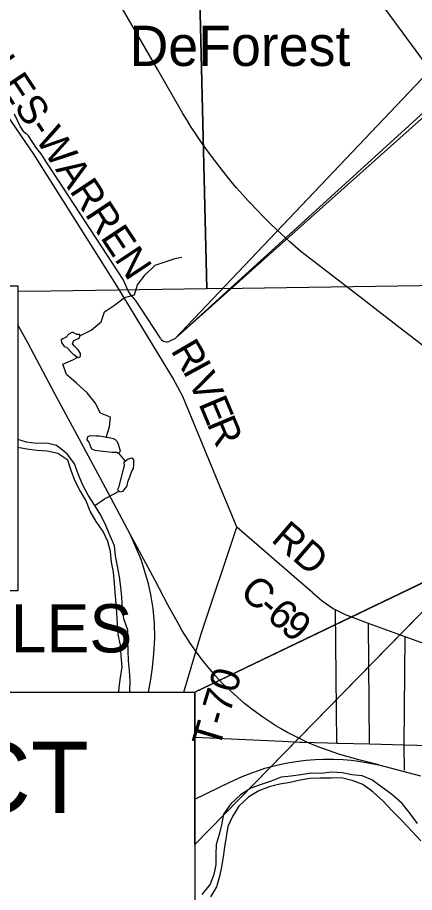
# Model space of a CAD drawing. Extents: x -37878.7 to -37844.7, y -19791.4 to -19769.4.
# Drawn here: x -37874.132 to -37873.351, y -19775.898 to -19774.18 of the extents above; entities that cross this region are included whole.
import ezdxf

# ---------------------------------------------------------------- set-up
doc = ezdxf.new("R2010")
doc.units = 0
for name, color, linetype in [('GM_X_City_Street', 7, 'Continuous'), ('GM_X_Corporation_Text', 7, 'Continuous'), ('GM_X_County_Road', 7, 'Continuous'), ('GM_X_County_Road_Text', 7, 'Continuous'), ('GM_X_Major_River', 7, 'Continuous'), ('GM_X_Minor_Lake', 7, 'Continuous'), ('GM_X_Minor_River', 7, 'Continuous'), ('GM_X_Rail_Line', 7, 'Continuous'), ('GM_X_Section', 7, 'Continuous'), ('GM_X_State_Route', 7, 'Continuous'), ('GM_X_Township_Road', 7, 'Continuous'), ('GM_X_Township_Road_Text', 7, 'Continuous'), ('GM_X_Unincorporated_Text', 7, 'Continuous'), ('SH_Data', 7, 'Continuous'), ('TX_P_1', 7, 'Continuous')]:
    doc.layers.add(name, color=color, linetype=linetype)

msp = doc.modelspace()

# ---------------------------------------------------------------- linework, layer by layer
at = {"layer": 'GM_X_City_Street'}
for points in [[(-37873.7707, -19775.3902), (-37873.7007, -19775.1805)], [(-37873.5041, -19775.6045), (-37873.5066, -19775.3431)], [(-37872.8734, -19775.5892), (-37872.8726, -19775.5759), (-37872.9176, -19775.5597), (-37872.9445, -19775.5501), (-37872.9852, -19775.5354), (-37873.0665, -19775.5062), (-37873.0787, -19775.5018), (-37873.1187, -19775.4876), (-37873.1691, -19775.4696), (-37873.1714, -19775.4688), (-37873.1939, -19775.4605), (-37873.2323, -19775.4464), (-37873.2421, -19775.4428), (-37873.301, -19775.4211), (-37873.3699, -19775.3957), (-37873.4414, -19775.3694), (-37873.4869, -19775.3527)], [(-37873.44, -19775.6062), (-37873.4414, -19775.3694)], [(-37873.3713, -19775.608), (-37873.3699, -19775.3957)], [(-37873.5222, -19775.6041), (-37873.5221, -19775.6041), (-37873.5041, -19775.6045), (-37873.5023, -19775.6046)], [(-37873.5023, -19775.6046), (-37873.44, -19775.6062), (-37873.3713, -19775.608), (-37873.2964, -19775.6099), (-37873.2652, -19775.6107), (-37873.2215, -19775.6119), (-37873.1559, -19775.6136), (-37873.1168, -19775.6146), (-37873.0689, -19775.6158), (-37872.9847, -19775.618), (-37872.9476, -19775.6187), (-37872.8753, -19775.6204)], [(-37873.3711, -19775.6581), (-37873.3713, -19775.608)]]:
    msp.add_lwpolyline(points, dxfattribs=at)
at = {"layer": 'GM_X_County_Road'}
for points in [[(-37873.7294, -19775.1112), (-37873.8071, -19774.9241), (-37873.8262, -19774.887), (-37873.9371, -19774.7051), (-37874.1, -19774.4477), (-37874.2922, -19774.1683), (-37874.3166, -19774.1461), (-37874.4179, -19774.0787)], [(-37873.5735, -19775.2907), (-37873.7007, -19775.1805), (-37873.7107, -19775.1562), (-37873.7294, -19775.1112)], [(-37873.5514, -19775.3098), (-37873.5733, -19775.2908), (-37873.5735, -19775.2907)], [(-37873.4869, -19775.3527), (-37873.5066, -19775.3431), (-37873.5113, -19775.3409), (-37873.5328, -19775.3259), (-37873.5512, -19775.31), (-37873.5514, -19775.3098)], [(-37873.7835, -19775.5929), (-37873.6118, -19775.601)], [(-37873.6118, -19775.601), (-37873.6117, -19775.601), (-37873.5769, -19775.6026), (-37873.572, -19775.6028)], [(-37873.572, -19775.6028), (-37873.5719, -19775.6028), (-37873.5222, -19775.6041)]]:
    msp.add_lwpolyline(points, dxfattribs=at)
at = {"layer": 'GM_X_Major_River'}
for points in [[(-37873.9135, -19775.4421), (-37873.9146, -19775.4228), (-37873.9147, -19775.4019), (-37873.9147, -19775.3826), (-37873.9228, -19775.3607), (-37873.9255, -19775.3395), (-37873.9267, -19775.3179), (-37873.929, -19775.2986), (-37873.9317, -19775.2778), (-37873.9355, -19775.257), (-37873.939, -19775.2366), (-37873.9413, -19775.2173), (-37873.9497, -19775.1978), (-37873.9581, -19775.1771), (-37873.9683, -19775.1572), (-37873.9797, -19775.1377), (-37873.9927, -19775.1175), (-37874.0033, -19775.098), (-37874.0117, -19775.0776), (-37874.0201, -19775.0562), (-37874.0341, -19775.0368), (-37874.0553, -19775.0201), (-37874.0744, -19775.0156), (-37874.0948, -19775.0164), (-37874.1146, -19775.0134), (-37874.131, -19775.0086)], [(-37873.949, -19775.2285), (-37873.9544, -19775.2089), (-37873.9635, -19775.1889), (-37873.9772, -19775.1691), (-37873.989, -19775.1493), (-37873.9974, -19775.1278), (-37874.0095, -19775.108), (-37874.019, -19775.0888), (-37874.0263, -19775.0692), (-37874.0331, -19775.0489), (-37874.0527, -19775.036), (-37874.0737, -19775.0312), (-37874.093, -19775.0297), (-37874.1139, -19775.0275), (-37874.131, -19775.0239)], [(-37873.9324, -19775.5045), (-37873.9321, -19775.4945), (-37873.9294, -19775.4755), (-37873.9261, -19775.4545), (-37873.9284, -19775.4333), (-37873.9296, -19775.4121), (-37873.9339, -19775.391), (-37873.9354, -19775.3697), (-37873.9363, -19775.3489), (-37873.9382, -19775.3296), (-37873.9397, -19775.3095), (-37873.9409, -19775.2902), (-37873.9429, -19775.269), (-37873.9471, -19775.2493), (-37873.949, -19775.2285)], [(-37873.9112, -19775.5045), (-37873.911, -19775.5032), (-37873.9103, -19775.483), (-37873.9119, -19775.4622), (-37873.9135, -19775.4421)], [(-37873.3456, -19775.7627), (-37873.3597, -19775.7429), (-37873.3753, -19775.7235), (-37873.3965, -19775.705), (-37873.4157, -19775.6914), (-37873.435, -19775.6766), (-37873.4541, -19775.6687), (-37873.4742, -19775.6668), (-37873.4936, -19775.6631), (-37873.5144, -19775.662), (-37873.5349, -19775.6643), (-37873.5542, -19775.6636), (-37873.5746, -19775.6671), (-37873.5938, -19775.6698), (-37873.6135, -19775.6717), (-37873.633, -19775.6794), (-37873.653, -19775.6862), (-37873.6733, -19775.6931), (-37873.6931, -19775.7065), (-37873.7124, -19775.7239), (-37873.7271, -19775.7444), (-37873.7309, -19775.7653), (-37873.7354, -19775.7844), (-37873.7414, -19775.8039), (-37873.7418, -19775.8236), (-37873.7417, -19775.843), (-37873.7459, -19775.8624), (-37873.753, -19775.8819), (-37873.7693, -19775.902)], [(-37873.3385, -19775.7964), (-37873.3567, -19775.7774), (-37873.3761, -19775.7569), (-37873.3954, -19775.7376), (-37873.4136, -19775.7179), (-37873.4333, -19775.7005), (-37873.453, -19775.6857), (-37873.472, -19775.6789), (-37873.4949, -19775.673), (-37873.515, -19775.6734), (-37873.5358, -19775.6735), (-37873.5562, -19775.6739), (-37873.5759, -19775.6777), (-37873.5955, -19775.682), (-37873.6163, -19775.6851), (-37873.637, -19775.6904), (-37873.6577, -19775.6981), (-37873.6771, -19775.7099), (-37873.6968, -19775.7282), (-37873.7092, -19775.7485), (-37873.7183, -19775.7685), (-37873.7217, -19775.7887), (-37873.7246, -19775.8092), (-37873.7273, -19775.8282), (-37873.731, -19775.8477), (-37873.7344, -19775.8667), (-37873.7408, -19775.887), (-37873.7525, -19775.9066)]]:
    msp.add_lwpolyline(points, dxfattribs=at)
at = {"layer": 'GM_X_Minor_Lake'}
for p, q in [((-37874.0359, -19774.8273), (-37874.0227, -19774.8407)), ((-37873.9756, -19775.0302), (-37873.946, -19775.033)), ((-37873.9219, -19775.0594), (-37873.9335, -19775.1025))]:
    msp.add_line(p, q, dxfattribs=at)
for points in [[(-37874.0227, -19774.8407), (-37874.0193, -19774.8429), (-37874.0151, -19774.8458), (-37874.012, -19774.8473), (-37874.0083, -19774.8453), (-37874.0084, -19774.8396), (-37874.0127, -19774.8321), (-37874.0158, -19774.8292), (-37874.0204, -19774.8243), (-37874.0235, -19774.8206), (-37874.0214, -19774.8141), (-37874.0109, -19774.8093), (-37874.0091, -19774.8062), (-37874.0092, -19774.8021), (-37874.0156, -19774.8018), (-37874.0225, -19774.7982), (-37874.0248, -19774.7982), (-37874.0308, -19774.8014), (-37874.036, -19774.8072), (-37874.0431, -19774.8108), (-37874.0461, -19774.8123), (-37874.0456, -19774.8188), (-37874.0421, -19774.8225), (-37874.0401, -19774.8255), (-37874.0359, -19774.8273)], [(-37873.946, -19775.033), (-37873.9369, -19775.0335), (-37873.9338, -19775.0361), (-37873.9293, -19775.0315), (-37873.9317, -19775.0247), (-37873.9326, -19775.0198), (-37873.9354, -19775.0126), (-37873.9393, -19775.0089), (-37873.9431, -19775.0067), (-37873.9488, -19775.0057), (-37873.9598, -19775.0037), (-37873.9709, -19775.002), (-37873.9777, -19775.0018), (-37873.9891, -19775.0013), (-37873.9943, -19775.0029), (-37873.9953, -19775.009), (-37873.9918, -19775.0138), (-37873.9886, -19775.0221), (-37873.9866, -19775.0266), (-37873.9801, -19775.0291), (-37873.9756, -19775.0302)], [(-37873.9335, -19775.1025), (-37873.9353, -19775.1067), (-37873.9307, -19775.1112), (-37873.9239, -19775.1095), (-37873.9165, -19775.0995), (-37873.9148, -19775.0915), (-37873.9112, -19775.0816), (-37873.9069, -19775.0705), (-37873.904, -19775.0651), (-37873.903, -19775.0575), (-37873.9032, -19775.0484), (-37873.9071, -19775.045), (-37873.9146, -19775.0471), (-37873.9194, -19775.0506), (-37873.9228, -19775.0537), (-37873.9219, -19775.0594)]]:
    msp.add_lwpolyline(points, dxfattribs=at)
at = {"layer": 'GM_X_Minor_River'}
for points in [[(-37874.0091, -19774.8049), (-37873.9874, -19774.7936), (-37873.9676, -19774.7773), (-37873.9612, -19774.7578), (-37873.9414, -19774.7444), (-37873.9213, -19774.7292), (-37873.9021, -19774.7239), (-37873.8957, -19774.7044), (-37873.8806, -19774.6851), (-37873.8613, -19774.6661), (-37873.8413, -19774.6592), (-37873.8217, -19774.6531), (-37873.8085, -19774.6505)], [(-37873.9575, -19775.0041), (-37873.9508, -19774.9837), (-37873.9493, -19774.9647), (-37873.9688, -19774.9564), (-37873.9791, -19774.9361), (-37873.995, -19774.9168), (-37874.0159, -19774.8978), (-37874.0355, -19774.8804), (-37874.0428, -19774.8605), (-37874.0233, -19774.8521), (-37874.0136, -19774.8465)], [(-37873.9194, -19775.0506), (-37873.9327, -19775.035)], [(-37873.9797, -19775.1377), (-37873.9607, -19775.1251), (-37873.9408, -19775.1145), (-37873.933, -19775.109)]]:
    msp.add_lwpolyline(points, dxfattribs=at)
at = {"layer": 'GM_X_Rail_Line'}
for points in [[(-37873.3122, -19774.8417), (-37873.3795, -19774.7897), (-37873.4588, -19774.7284), (-37873.5577, -19774.6519), (-37873.5746, -19774.6392), (-37873.5963, -19774.6202), (-37873.6133, -19774.6044), (-37873.6329, -19774.5861), (-37873.6457, -19774.5735), (-37873.6635, -19774.5552), (-37873.6712, -19774.5467), (-37873.6787, -19774.5388), (-37873.6898, -19774.527), (-37873.7014, -19774.5143), (-37873.7093, -19774.5048), (-37873.7193, -19774.4925), (-37873.7287, -19774.4801), (-37873.742, -19774.463), (-37873.7544, -19774.4468), (-37873.7685, -19774.4271), (-37873.7809, -19774.409), (-37873.7902, -19774.3946), (-37873.7977, -19774.3827), (-37873.807, -19774.3678), (-37873.8563, -19774.2826), (-37873.8975, -19774.2112), (-37873.9462, -19774.1259)], [(-37873.9096, -19775.1957), (-37873.9644, -19775.0935), (-37874.0155, -19774.9987), (-37874.0585, -19774.9186), (-37874.1117, -19774.8187), (-37874.131, -19774.7828)], [(-37873.4214, -19775.6474), (-37873.4607, -19775.6372), (-37873.4979, -19775.6271), (-37873.5225, -19775.6187), (-37873.5425, -19775.6113), (-37873.5614, -19775.6035), (-37873.6021, -19775.583), (-37873.6147, -19775.576), (-37873.6237, -19775.5707), (-37873.6497, -19775.5538), (-37873.6688, -19775.5399), (-37873.6847, -19775.5276), (-37873.6989, -19775.5153), (-37873.7139, -19775.5016), (-37873.7286, -19775.4873), (-37873.7423, -19775.4726), (-37873.7533, -19775.4603), (-37873.7638, -19775.4476), (-37873.773, -19775.4357), (-37873.7801, -19775.4261), (-37873.7925, -19775.4082), (-37873.8018, -19775.3939), (-37873.8088, -19775.3825), (-37873.8147, -19775.3714), (-37873.8354, -19775.3342), (-37873.8614, -19775.2855), (-37873.9014, -19775.211), (-37873.9096, -19775.1957)], [(-37873.8746, -19775.5045), (-37873.8698, -19775.4796), (-37873.8663, -19775.4561), (-37873.8636, -19775.4289), (-37873.8619, -19775.3988), (-37873.8626, -19775.3692), (-37873.865, -19775.3402), (-37873.87, -19775.313), (-37873.8746, -19775.2916), (-37873.8814, -19775.2675), (-37873.8889, -19775.2443), (-37873.9096, -19775.1957)], [(-37873.7835, -19775.7147), (-37873.7147, -19775.6816), (-37873.7003, -19775.6747), (-37873.6899, -19775.6703), (-37873.6795, -19775.666), (-37873.6694, -19775.6621), (-37873.6583, -19775.6583), (-37873.6454, -19775.6541), (-37873.6324, -19775.6506), (-37873.6195, -19775.6474), (-37873.6041, -19775.644), (-37873.5927, -19775.6421), (-37873.5794, -19775.64), (-37873.5642, -19775.6384), (-37873.5465, -19775.637), (-37873.5305, -19775.6362), (-37873.5103, -19775.6362), (-37873.4916, -19775.6369), (-37873.4759, -19775.638), (-37873.4614, -19775.6402), (-37873.446, -19775.6424), (-37873.4214, -19775.6474)], [(-37873.4214, -19775.6474), (-37873.3397, -19775.6689)]]:
    msp.add_lwpolyline(points, dxfattribs=at)
at = {"layer": 'GM_X_Section'}
for points in [[(-37872.1869, -19774.0898), (-37872.1703, -19774.6795), (-37872.5802, -19774.6904), (-37872.9663, -19774.7007), (-37873.2969, -19774.7059), (-37873.6902, -19774.7116), (-37873.7599, -19774.7127), (-37873.7756, -19774.0615), (-37873.0522, -19774.0492), (-37872.2676, -19774.0343)], [(-37875.1274, -19774.7063), (-37875.1291, -19774.6153), (-37875.1389, -19774.0828), (-37873.8639, -19774.0628), (-37873.7756, -19774.0615), (-37873.7599, -19774.7127), (-37874.0664, -19774.7168), (-37874.131, -19774.7175)]]:
    msp.add_lwpolyline(points, dxfattribs=at)
at = {"layer": 'GM_X_State_Route'}
msp.add_lwpolyline([(-37873.9525, -19773.4359), (-37873.9516, -19773.437), (-37873.929, -19773.4672), (-37873.8814, -19773.533), (-37873.8208, -19773.6151), (-37873.7352, -19773.7323), (-37873.6648, -19773.8255), (-37873.6559, -19773.8369), (-37873.6317, -19773.8694), (-37873.5871, -19773.9264), (-37873.5479, -19773.9782), (-37873.4895, -19774.0537), (-37873.4651, -19774.0863), (-37873.3999, -19774.1756), (-37873.3324, -19774.2675), (-37873.2991, -19774.3122), (-37873.2647, -19774.3592), (-37873.2311, -19774.4048), (-37873.1974, -19774.4513), (-37873.1286, -19774.5429), (-37873.063, -19774.6349), (-37873.0449, -19774.6594)], dxfattribs=at)
at = {"layer": 'GM_X_Township_Road'}
msp.add_lwpolyline([(-37873.8048, -19775.5045), (-37873.7707, -19775.3902)], dxfattribs=at)
at = {"layer": 'SH_Data'}
for p, q in [((-37874.1266, -19774.3928), (-37874.1382, -19774.3696)), ((-37874.1193, -19774.4039), (-37874.1266, -19774.3928)), ((-37874.1135, -19774.4089), (-37874.1162, -19774.4071)), ((-37874.096, -19774.4342), (-37874.1104, -19774.4121)), ((-37874.0844, -19774.4492), (-37874.096, -19774.4342)), ((-37874.0741, -19774.465), (-37874.0844, -19774.4492)), ((-37874.0641, -19774.4805), (-37874.0741, -19774.465)), ((-37873.9245, -19774.6944), (-37874.0641, -19774.4805)), ((-37873.9143, -19774.7162), (-37873.9245, -19774.6944)), ((-37873.9091, -19774.7241), (-37873.9143, -19774.7162)), ((-37873.8997, -19774.7349), (-37873.9091, -19774.7241)), ((-37873.8895, -19774.7505), (-37873.8997, -19774.7349)), ((-37873.8509, -19774.8095), (-37873.8895, -19774.7505)), ((-37873.8226, -19774.8103), (-37873.8315, -19774.8148))]:
    msp.add_line(p, q, dxfattribs=at)
for centre, radius, start, end in [((-37874.1098, -19774.3977), 0.0113, 213.1391, 235.7633), ((-37874.1199, -19774.4183), 0.0113, 33.1391, 55.7633), ((-37873.8383, -19774.8013), 0.0151, 213.1391, 296.7023)]:
    msp.add_arc(centre, radius, start, end, dxfattribs=at)
at = {"layer": 'TX_P_1'}
for p, q in [((-37871.7188, -19772.5985), (-37873.8226, -19774.8103)), ((-37873.8226, -19774.8103), (-37871.7188, -19772.898)), ((-37876.1098, -19774.7063), (-37874.131, -19774.7063)), ((-37874.131, -19774.7063), (-37874.131, -19775.3053)), ((-37873.2311, -19775.2398), (-37873.7835, -19775.804)), ((-37873.2311, -19775.2398), (-37873.7835, -19775.5045)), ((-37874.131, -19775.3053), (-37876.1098, -19775.3053)), ((-37875.7623, -19775.5045), (-37873.7835, -19775.5045)), ((-37873.7835, -19775.5045), (-37873.7835, -19776.1036))]:
    msp.add_line(p, q, dxfattribs=at)
for points in [[(-37871.7188, -19772.5985), (-37873.8226, -19774.8103), (-37871.7188, -19772.9363)], [(-37873.7835, -19775.5045), (-37873.2311, -19775.2398), (-37873.7835, -19775.804)]]:
    msp.add_lwpolyline(points, close=True, dxfattribs=at)

# ---------------------------------------------------------------- texts
at = {"layer": 'GM_X_Corporation_Text'}
msp.add_text('NILES', height=0.0947, rotation=0, dxfattribs=at).set_placement((-37874.2722, -19775.4265))
at = {"layer": 'GM_X_County_Road_Text'}
for s, height, rotation, p in [('NILES-WARREN', 0.056818, 303.4615, (-37874.2333, -19774.2135)), ('R', 0.0568, 300.2208, (-37873.8316, -19774.8333)), ('I', 0.0568, 298.5307, (-37873.8083, -19774.8732)), ('V', 0.0568, 294.9716, (-37873.7976, -19774.8929)), ('E', 0.0568, 292.8058, (-37873.7767, -19774.9377)), ('R', 0.0568, 292.7125, (-37873.7603, -19774.9769)), ('RD', 0.05682, 319.1852, (-37873.6354, -19775.207)), ('C', 0.0568, 318.8225, (-37873.6975, -19775.3123)), ('-', 0.0568, 318.8873, (-37873.6623, -19775.3431)), ('6', 0.0568, 319.155, (-37873.6445, -19775.3586)), ('9', 0.0568, 320.2321, (-37873.6172, -19775.3823))]:
    msp.add_text(s, height=height, rotation=rotation, dxfattribs=at).set_placement(p)
at = {"layer": 'GM_X_Township_Road_Text'}
msp.add_text('T-70', height=0.05682, rotation=73.1311, dxfattribs=at).set_placement((-37873.7356, -19775.6175))
at = {"layer": 'GM_X_Unincorporated_Text'}
msp.add_text('DeForest', height=0.07898, rotation=0, dxfattribs=at).set_placement((-37873.9117, -19774.2747))
at = {"layer": 'TX_P_1'}
msp.add_text('RESUME PROJECT', height=0.14, rotation=360, dxfattribs=at).set_placement((-37875.7183, -19775.7421))

doc.saveas('drawing.dxf')
